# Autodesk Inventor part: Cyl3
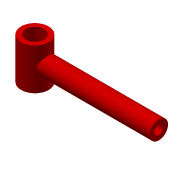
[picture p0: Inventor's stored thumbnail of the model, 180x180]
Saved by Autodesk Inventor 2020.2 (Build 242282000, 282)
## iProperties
Created: 2005-10
Part Number: Cyl3
Document SubType Name: Modeling
Designer: F.Stasiak
Density: 1 g/cm^3
Material: Ogólny
Appearance: Czerwony
Manager: www.cadconsulting.pl
Company: Fabian Stasiak CAD Consulting
Author: F.Stasiak
Subject: Zbiór ćwiczeń. Autodesk Inventor 2020. Kurs podstawowy
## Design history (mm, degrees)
sketch "Szkic1"
  geometry: L1 (236.669, 0)-(506.669, 0); L2 (506.669, 0)-(506.669, 20); L3 (506.669, 20)-(236.669, 20); L4 (236.669, 20)-(236.669, 0); C1 r 30 at (236.669, 20); 2 further points
  constraints: 8 end point, 2 coincident, 2 parallel, 1 centre point, 1 horizontal, 1 perpendicular, 1 vertical alignment, 2 other
  dimensions: "d0" = 270 distance of L1.start L1.end; "d1" = 20 distance of L1.end L2.end; "d2" = 60 diameter of C1
revolve "Obrót1" stored, may be unused: angle "d3" = 90 deg
extrude "Wyciągnięcie proste1" join sketch "Szkic1" stored distance "d4" = 90; taper "d5" = 0 deg
extrude "Wyciągnięcie proste2" cut sketch "Szkic1" extent not by distance; stored distance "d6" = 80; taper "d7" = 0 deg
sketch "Szkic2"
  geometry: C1 r 20 at (0, 0) reference; C2 r 10 at (0, 0)
  constraints: 1 centre point, 1 coincident
  dimensions: "d8" = 20 diameter of C2
extrude "Wyciągnięcie proste3" cut sketch "Szkic2" distance "d9" = 245; taper "d10" = 0 deg
node "Bryła1"
node "Korpusy bryłowe"
node "Korpusy powierzchniowe"
